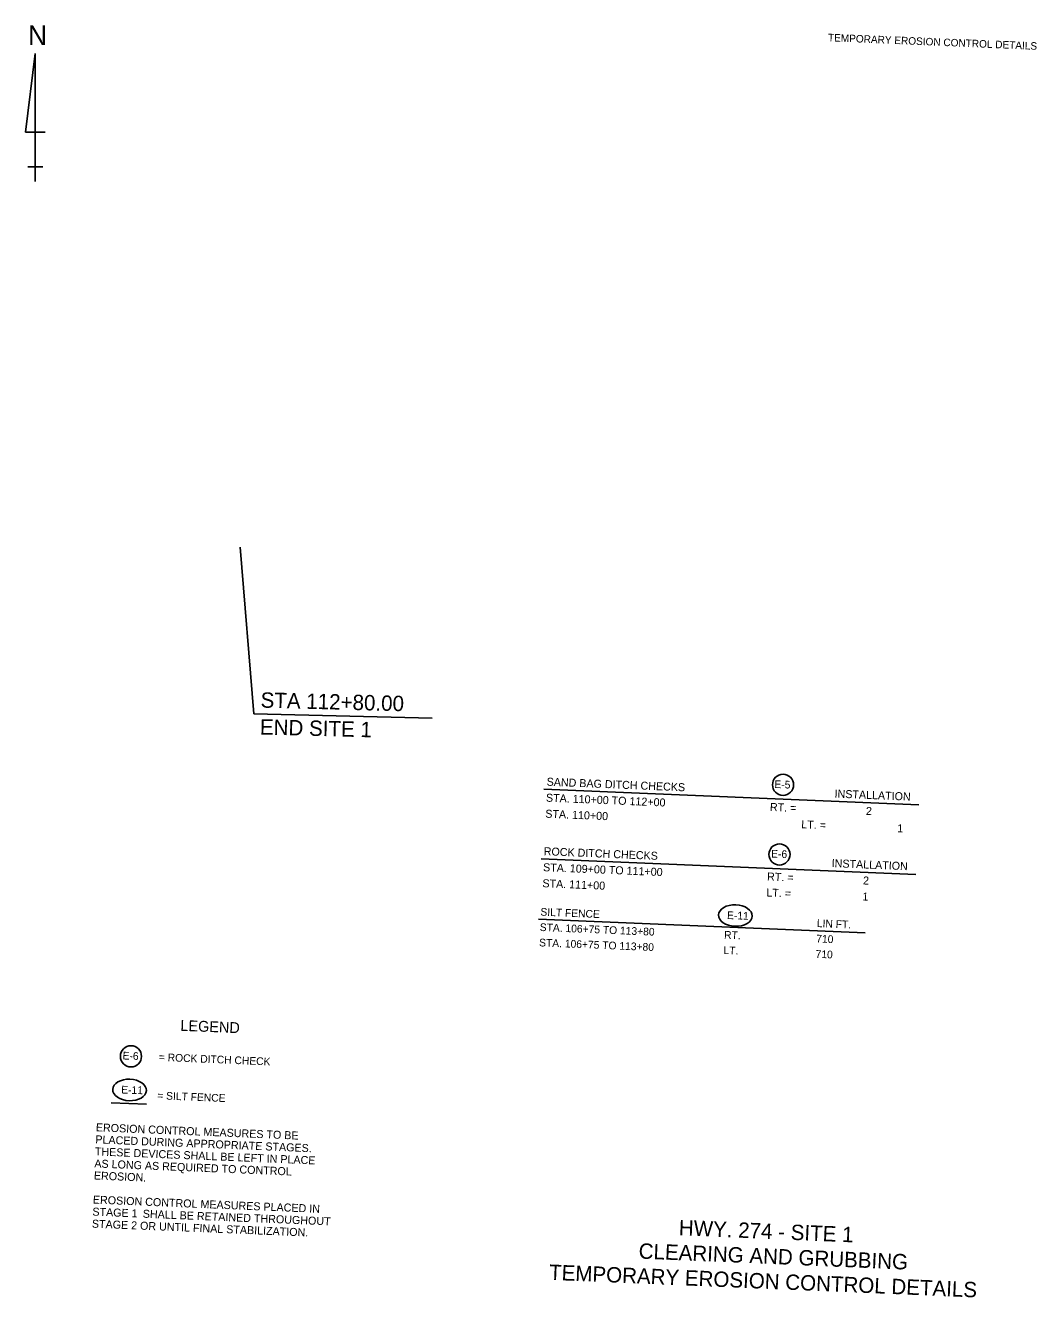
# Model space of a CAD drawing. Extents: x 1141845 to 1143440, y 1657054 to 1658137.
# Drawn here: x 1142650 to 1143440, y 1657054 to 1658047 of the extents above; entities that cross this region are included whole.
import ezdxf

# ---------------------------------------------------------------- set-up
doc = ezdxf.new("R2010")
doc.units = 0
for name, color, linetype in [('Default', 7, 'Continuous'), ('S_PRIMARY_CTL', 7, 'Continuous'), ('S_RAILROAD', 7, 'Continuous'), ('S_SIDE_DRAIN', 7, 'Continuous')]:
    doc.layers.add(name, color=color, linetype=linetype)

msp = doc.modelspace()

# ---------------------------------------------------------------- linework, layer by layer
at = {"layer": 'Default'}
for p, q in [((1142657.85, 1658025.37), (1142650.16, 1657963.83)), ((1142657.85, 1657925.37), (1142657.85, 1658025.37)), ((1142657.85, 1658025.37), (1142657.85, 1657948.45)), ((1142650.16, 1657963.83), (1142665.55, 1657963.83)), ((1142657.85, 1657925.37), (1142657.85, 1657948.45)), ((1142657.85, 1657936.91), (1142652.08, 1657936.91)), ((1142652.08, 1657936.91), (1142663.62, 1657936.91)), ((1142657.85, 1657925.37), (1142657.85, 1657936.91)), ((1143054.96, 1657450.86), (1143347.6, 1657438.75)), ((1143052.72, 1657396.57), (1143345.35, 1657384.46))]:
    msp.add_line(p, q, dxfattribs=at)
msp.add_circle((1143241.63, 1657454.35), 8.26, dxfattribs=at)
at = {"layer": 'S_PRIMARY_CTL'}
for p, q in [((1142828.5, 1657509.85), (1142817.87, 1657639.91)), ((1142828.5, 1657509.85), (1142967.66, 1657506.29)), ((1143050.77, 1657349.41), (1143305.77, 1657338.86))]:
    msp.add_line(p, q, dxfattribs=at)
at = {"layer": 'S_RAILROAD'}
msp.add_lwpolyline([(1142716.96, 1657206.17), (1142744.74, 1657205.03)], dxfattribs=at)
for centre in [(1143238.81, 1657399.98), (1142732.52, 1657242.37)]:
    msp.add_circle(centre, 8.26, dxfattribs=at)
for centre in [(1143204.4, 1657352.3), (1142731.44, 1657216.12)]:
    msp.add_ellipse(centre, major_axis=(13.14, -0.49), ratio=0.638788, dxfattribs=at)

# ---------------------------------------------------------------- texts
at = {"layer": 'Default'}
msp.add_text('N', height=15.38, dxfattribs=at).set_placement((1142652.22, 1658031.78))
for s, height, p in [('SAND BAG DITCH CHECKS', 6.25, (1143056.92, 1657453.72)), ('E-5 ', 5.999, (1143234.77, 1657451.91)), ('STA. 110+00 TO 112+00 ', 6.25, (1143056.4, 1657441.23)), ('INSTALLATION', 6.25, (1143281.73, 1657444.42)), ('STA. 110+00', 6.25, (1143055.89, 1657428.74)), ('RT. = ', 6.25, (1143231.25, 1657434)), ('2', 6.25, (1143306.19, 1657430.9)), ('LT. =', 6.25, (1143255.72, 1657420.47)), ('1', 6.25, (1143330.65, 1657417.37)), ('ROCK DITCH CHECKS', 6.25, (1143054.68, 1657399.43)), ('INSTALLATION', 6.25, (1143279.48, 1657390.13)), ('STA. 109+00 TO 111+00 ', 6.25, (1143054.16, 1657386.94)), ('RT. = ', 6.25, (1143229.01, 1657379.7)), ('STA. 111+00', 6.25, (1143053.64, 1657374.45)), ('2', 6.25, (1143303.94, 1657376.6)), ('LT. =', 6.25, (1143228.49, 1657367.21)), ('1', 6.25, (1143303.43, 1657364.11))]:
    msp.add_text(s, height=height, rotation=357.63112, dxfattribs=at).set_placement(p)
at = {"layer": 'S_PRIMARY_CTL'}
for s, height, rotation, p in [('STA 112+80.00', 12, 358.53458, (1142833.62, 1657514.63)), ('END SITE 1', 12, 358.53458, (1142833.09, 1657493.64)), ('SILT FENCE', 6, 357.63112, (1143052.1, 1657352.25)), ('STA. 106+75 TO 113+80 ', 6, 357.63112, (1143051.6, 1657340.26)), ('LIN FT.', 6, 357.63112, (1143267.91, 1657343.32)), ('STA. 106+75 TO 113+80', 6, 357.63112, (1143051.11, 1657328.27)), ('RT. ', 6, 357.63112, (1143195.48, 1657334.31)), ('710', 6, 357.63112, (1143267.42, 1657331.33)), ('LT.', 6, 357.63112, (1143194.98, 1657322.32)), ('710', 6, 357.63112, (1143266.92, 1657319.34)), ('= ROCK DITCH CHECK', 6, 357.63113, (1142754.23, 1657238.87)), ('= SILT FENCE', 6, 357.63113, (1142752.99, 1657208.9)), ('EROSION CONTROL MEASURES TO BE', 6.25, 357.63113, (1142705.04, 1657183.9)), ('PLACED DURING APPROPRIATE STAGES. ', 6.25, 357.63113, (1142704.65, 1657174.5)), ('THESE DEVICES SHALL BE LEFT IN PLACE ', 6.25, 357.63113, (1142704.26, 1657165.09)), ('AS LONG AS REQUIRED TO CONTROL ', 6.25, 357.63113, (1142703.88, 1657155.69)), ('EROSION.', 6.25, 357.63113, (1142703.49, 1657146.29)), ('EROSION CONTROL MEASURES PLACED IN ', 6.25, 357.63113, (1142702.71, 1657127.49)), ('STAGE 1 ', 6.25, 357.63113, (1142702.32, 1657118.08)), ('SHALL BE RETAINED THROUGHOUT ', 6.25, 357.63113, (1142741.66, 1657116.46)), ('STAGE 2 OR UNTIL FINAL STABILIZATION.', 6.25, 357.63113, (1142701.93, 1657108.68)), ('HWY. 274 - SITE 1', 12, 357.63112, (1143160.05, 1657102.77)), ('CLEARING AND GRUBBING ', 12, 357.63112, (1143128.7, 1657084.55)), ('TEMPORARY EROSION CONTROL DETAILS', 12, 357.63112, (1143058.74, 1657067.93))]:
    msp.add_text(s, height=height, rotation=rotation, dxfattribs=at).set_placement(p)
at = {"layer": 'S_RAILROAD'}
for s, height, rotation, p in [('E-6 ', 5.999, 358.03167, (1143232.23, 1657397.6)), ('E-11', 5.999, 357.84549, (1143197.8, 1657349.6)), ('LEGEND', 8.439, 357.63113, (1142770.99, 1657262.34)), ('E-6 ', 5.999, 358.03167, (1142725.94, 1657239.98)), ('E-11', 5.999, 357.84549, (1142724.83, 1657213.42))]:
    msp.add_text(s, height=height, rotation=rotation, dxfattribs=at).set_placement(p)
at = {"layer": 'S_SIDE_DRAIN'}
msp.add_text('TEMPORARY EROSION CONTROL DETAILS', height=5.862, rotation=357.63112, dxfattribs=at).set_placement((1143276.6, 1658034.87))

doc.saveas('drawing.dxf')
